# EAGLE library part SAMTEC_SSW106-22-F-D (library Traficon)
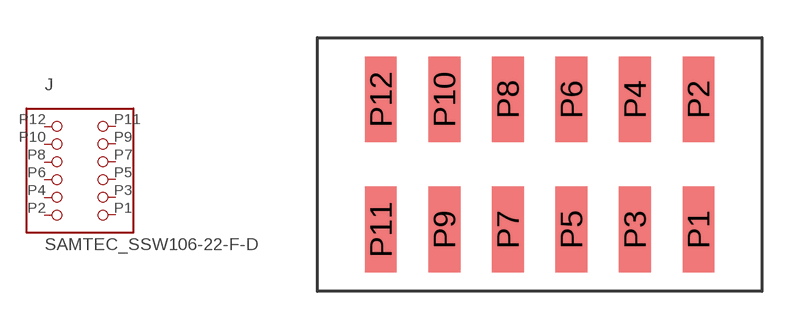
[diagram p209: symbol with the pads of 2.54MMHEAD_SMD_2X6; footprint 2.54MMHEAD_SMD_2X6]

Designator prefix J

## SAMTEC_SSW106-22-F-D  [2.54MMHEAD_SMD_2X6]
P1  1  pas
P2  2  pas
P3  3  pas
P4  4  pas
P5  5  pas
P6  6  pas
P7  7  pas
P8  8  pas
P9  9  pas
P10  10  pas
P11  11  pas
P12  12  pas

## Footprint 2.54MMHEAD_SMD_2X6 (pad centres in mm)
smd 1.27 x 3.43: P1 6.35,-2.605; P2 6.35,2.605; P3 3.81,-2.605; P4 3.81,2.605; P5 1.27,-2.605; P6 1.27,2.605; P7 -1.27,-2.605; P8 -1.27,2.605; P9 -3.81,-2.605; P10 -3.81,2.605; P11 -6.35,-2.605; P12 -6.35,2.605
